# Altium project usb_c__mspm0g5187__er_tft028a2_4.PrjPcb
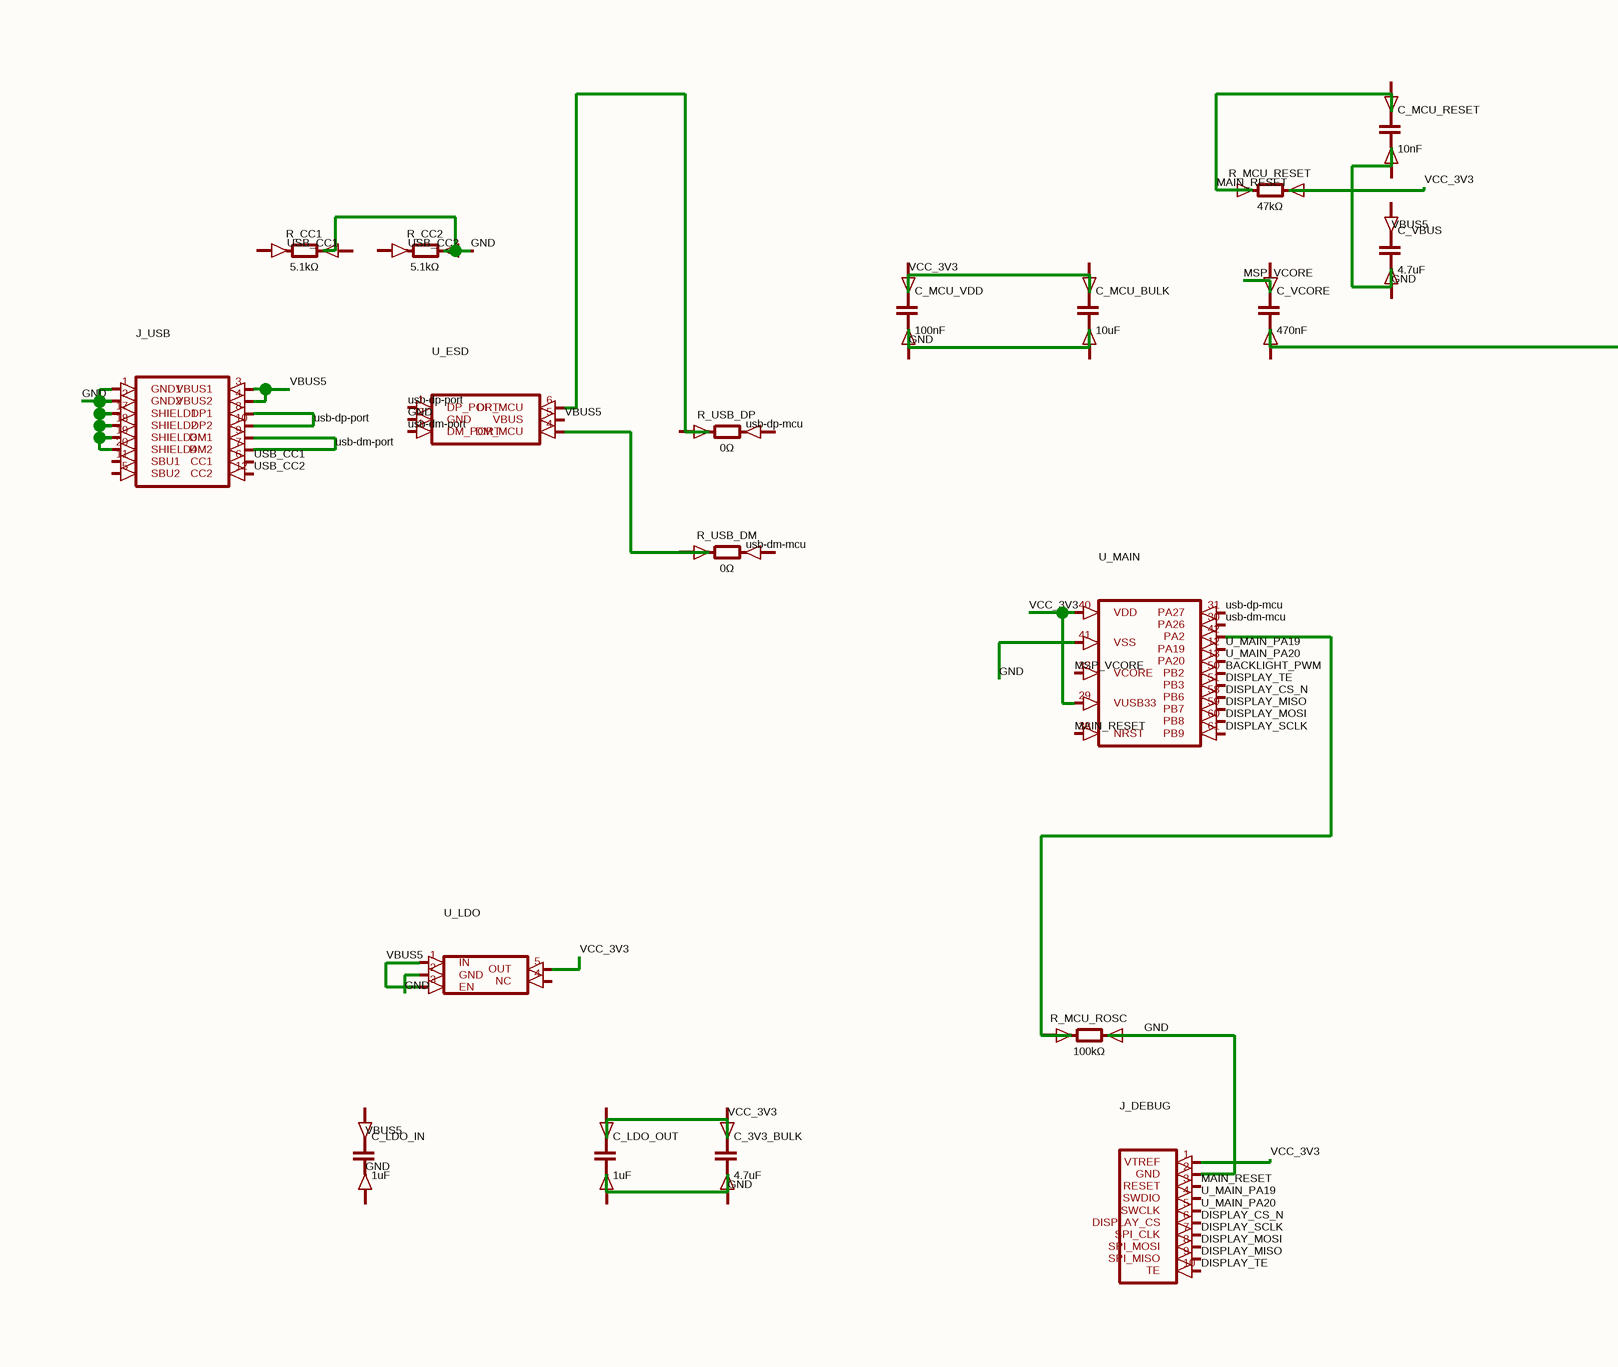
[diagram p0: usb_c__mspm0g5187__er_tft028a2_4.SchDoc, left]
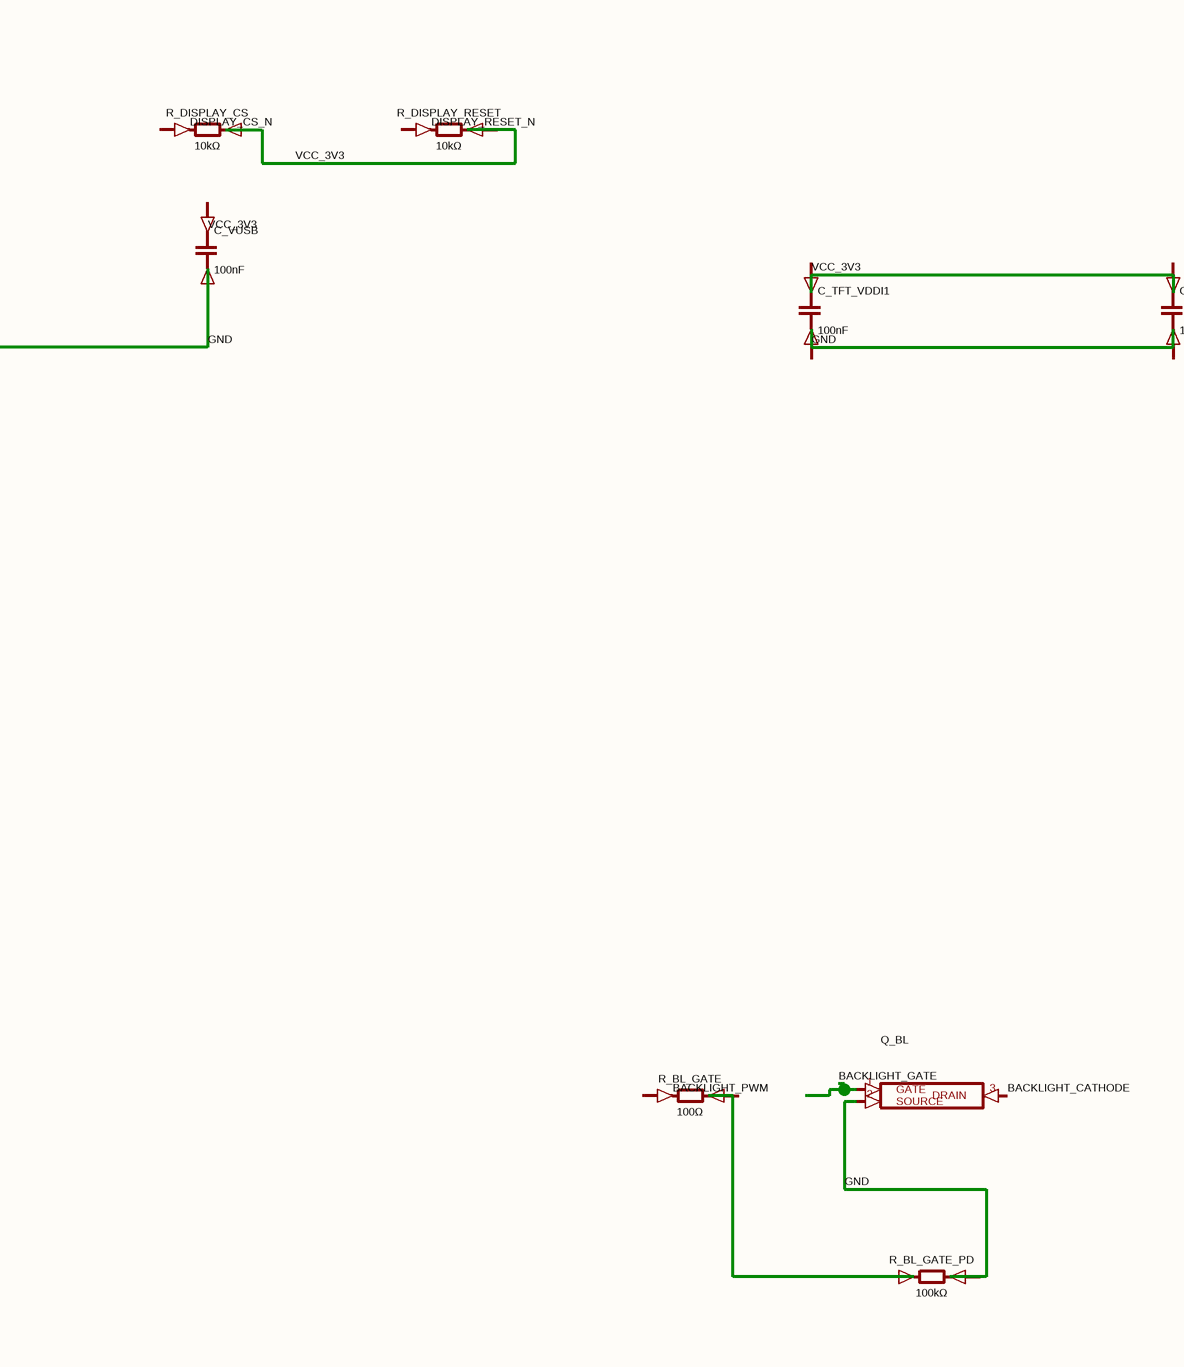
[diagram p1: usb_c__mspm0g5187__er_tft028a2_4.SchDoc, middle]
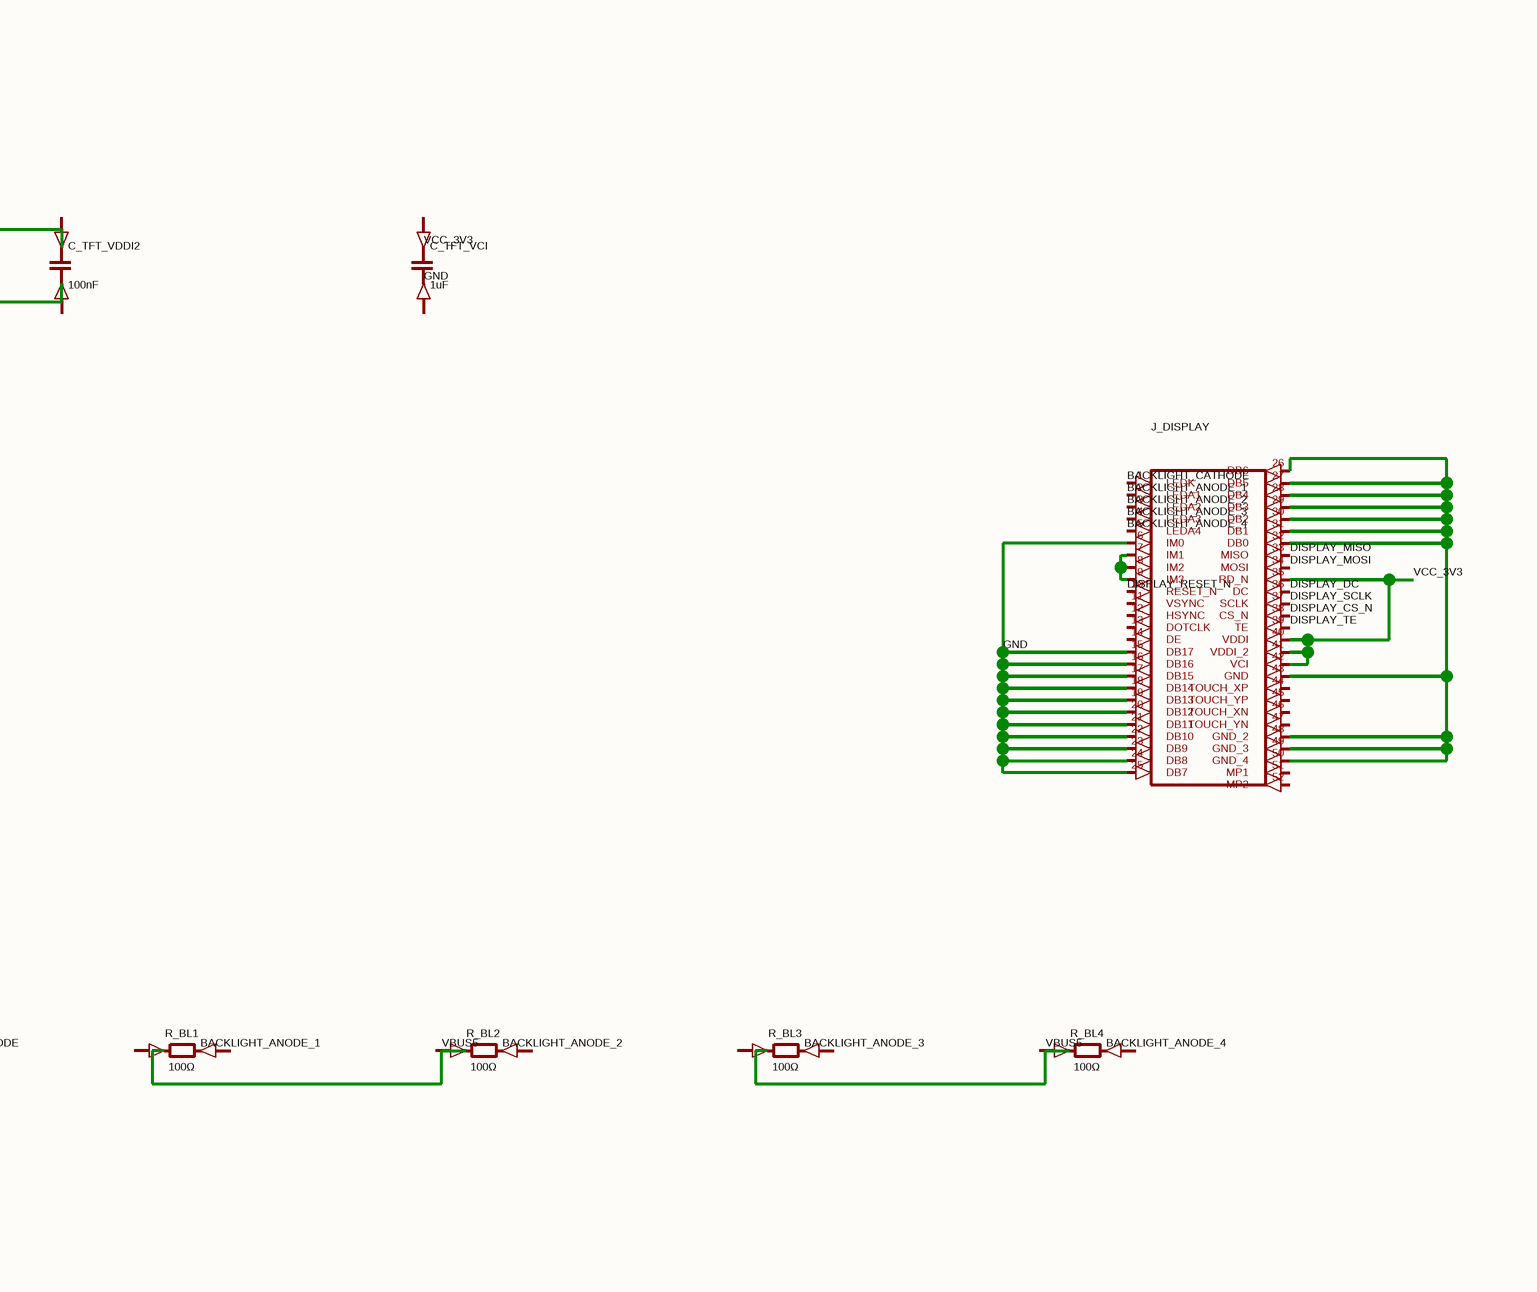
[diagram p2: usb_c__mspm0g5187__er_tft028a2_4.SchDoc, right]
1 sheet, 33 parts. Net scope: global (net labels, ports and power ports of the same name join across sheets).
Board file: usb_c__mspm0g5187__er_tft028a2_4.PcbDoc

## Sheet usb_c__mspm0g5187__er_tft028a2_4.SchDoc
size 389 x 150 mm

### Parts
C_3V3_BULK  4.7uF
C_LDO_IN  1uF
C_LDO_OUT  1uF
C_MCU_BULK  10uF
C_MCU_RESET  10nF
C_MCU_VDD  100nF
C_TFT_VCI  1uF
C_TFT_VDDI1  100nF
C_TFT_VDDI2  100nF
C_VBUS  4.7uF
C_VCORE  470nF
C_VUSB  100nF
J_DEBUG  (no value)
J_DISPLAY  (no value)
J_USB  (no value)
Q_BL  (no value)
R_BL1  100Ω
R_BL2  100Ω
R_BL3  100Ω
R_BL4  100Ω
R_BL_GATE  100Ω
R_BL_GATE_PD  100kΩ
R_CC1  5.1kΩ
R_CC2  5.1kΩ
R_DISPLAY_CS  10kΩ
R_DISPLAY_RESET  10kΩ
R_MCU_RESET  47kΩ
R_MCU_ROSC  100kΩ
R_USB_DM  0Ω
R_USB_DP  0Ω
U_ESD  (no value)
U_LDO  (no value)
U_MAIN  (no value)

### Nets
BACKLIGHT_ANODE_1: J_DISPLAY.2(LEDA1)
BACKLIGHT_ANODE_2: J_DISPLAY.3(LEDA2)
BACKLIGHT_ANODE_3: J_DISPLAY.4(LEDA3)
BACKLIGHT_ANODE_4: J_DISPLAY.5(LEDA4)
BACKLIGHT_CATHODE: J_DISPLAY.1(LEDK) Q_BL.3(DRAIN)
BACKLIGHT_GATE: Q_BL.1(GATE)
BACKLIGHT_PWM: U_MAIN.50(PB2)
DISPLAY_CS_N: J_DEBUG.6(DISPLAY_CS) J_DISPLAY.38(CS_N) U_MAIN.58(PB6)
DISPLAY_DC: J_DISPLAY.36(DC)
DISPLAY_MISO: J_DEBUG.9(SPI_MISO) J_DISPLAY.33(MISO) U_MAIN.59(PB7)
DISPLAY_MOSI: J_DEBUG.8(SPI_MOSI) J_DISPLAY.34(MOSI) U_MAIN.60(PB8)
DISPLAY_RESET_N: J_DISPLAY.10(RESET_N)
DISPLAY_SCLK: J_DEBUG.7(SPI_CLK) J_DISPLAY.37(SCLK) U_MAIN.61(PB9)
DISPLAY_TE: J_DEBUG.10(TE) J_DISPLAY.39(TE) U_MAIN.51(PB3)
GND: C_VUSB.2(cathode) J_DEBUG.1(VTREF) J_DEBUG.2(GND) J_DISPLAY.6(IM0) J_DISPLAY.15(DB17) J_DISPLAY.16(DB16) J_DISPLAY.17(DB15) J_DISPLAY.18(DB14) J_DISPLAY.19(DB13) J_DISPLAY.20(DB12) J_DISPLAY.21(DB11) J_DISPLAY.22(DB10) J_DISPLAY.23(DB9) J_DISPLAY.24(DB8) J_DISPLAY.25(DB7) J_DISPLAY.35(RD_N) J_DISPLAY.40(VDDI) J_DISPLAY.41(VDDI_2) J_DISPLAY.42(VCI) J_USB.1(GND1) J_USB.2(GND2) J_USB.3(VBUS1) J_USB.4(VBUS2) J_USB.17(SHIELD1) J_USB.18(SHIELD2) J_USB.19(SHIELD3) J_USB.20(SHIELD4) Q_BL.2(SOURCE) R_BL_GATE_PD.2(cathode) R_DISPLAY_CS.2(cathode) R_DISPLAY_RESET.2(cathode) R_MCU_RESET.2(cathode) R_MCU_ROSC.2(cathode) U_ESD.2(GND) U_ESD.5(VBUS) U_LDO.1(IN) U_LDO.2(GND) U_LDO.3(EN) U_LDO.5(OUT) U_MAIN.29(VUSB33) U_MAIN.40(VDD) U_MAIN.41(VSS)  [also labelled VBUS5, VCC_3V3]
MAIN_RESET: J_DEBUG.3(RESET) R_MCU_RESET.1(anode) U_MAIN.38(NRST)
MSP_VCORE: U_MAIN.32(VCORE)
U_MAIN_PA19: J_DEBUG.4(SWDIO) U_MAIN.12(PA19)
U_MAIN_PA20: J_DEBUG.5(SWCLK) U_MAIN.13(PA20)
usb-dm-mcu: U_MAIN.30(PA26)
usb-dm-port: J_USB.7(DM2) J_USB.9(DM1) U_ESD.3(DM_PORT)
usb-dp-mcu: U_MAIN.31(PA27)
usb-dp-port: J_USB.8(DP1) J_USB.10(DP2) U_ESD.1(DP_PORT)
USB_CC1: J_USB.6(CC1)
USB_CC2: J_USB.12(CC2)
NetJ_DISPLAY_7: J_DISPLAY.7(IM1) J_DISPLAY.8(IM2) J_DISPLAY.9(IM3)
NetJ_DISPLAY_26: J_DISPLAY.26(DB6) J_DISPLAY.27(DB5) J_DISPLAY.28(DB4) J_DISPLAY.29(DB3) J_DISPLAY.30(DB2) J_DISPLAY.31(DB1) J_DISPLAY.32(DB0) J_DISPLAY.43(GND) J_DISPLAY.48(GND_2) J_DISPLAY.49(GND_3) J_DISPLAY.50(GND_4)
NetR_MCU_ROSC_1: R_MCU_ROSC.1(anode) U_MAIN.42(PA2)
NetR_USB_DM_1: R_USB_DM.1(anode) U_ESD.4(DM_MCU)

Not connected (* = marked no-connect by the designer): C_3V3_BULK 1(anode) 2(cathode); C_LDO_IN 1(anode) 2(cathode); C_LDO_OUT 1(anode) 2(cathode); C_MCU_BULK 1(anode) 2(cathode); C_MCU_RESET 1(anode) 2(cathode); C_MCU_VDD 1(anode) 2(cathode); C_TFT_VCI 1(anode) 2(cathode); C_TFT_VDDI1 1(anode) 2(cathode); C_TFT_VDDI2 1(anode) 2(cathode); C_VBUS 1(anode) 2(cathode); C_VCORE 1(anode) 2(cathode); C_VUSB 1(anode); J_DISPLAY 11(VSYNC) 12(HSYNC) 13(DOTCLK) 14(DE) 44(TOUCH_XP) 45(TOUCH_YP) 46(TOUCH_XN) 47(TOUCH_YN) 51(MP1) 52(MP2); J_USB 5(SBU2) 11(SBU1); R_BL1 1(anode) 2(cathode); R_BL2 1(anode) 2(cathode); R_BL3 1(anode) 2(cathode); R_BL4 1(anode) 2(cathode); R_BL_GATE 1(anode) 2(cathode); R_BL_GATE_PD 1(anode); R_CC1 1(anode) 2(cathode); R_CC2 1(anode) 2(cathode); R_DISPLAY_CS 1(anode); R_DISPLAY_RESET 1(anode); R_USB_DM 2(cathode); R_USB_DP 1(anode) 2(cathode); U_ESD 6(DP_MCU); U_LDO 4(NC)

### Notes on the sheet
- Labels drawn without touching a wire or pin: BACKLIGHT_ANODE_1, BACKLIGHT_ANODE_2, BACKLIGHT_ANODE_3, BACKLIGHT_ANODE_4, BACKLIGHT_PWM, DISPLAY_CS_N, DISPLAY_RESET_N, GND, usb-dm-mcu, usb-dp-mcu, USB_CC1, USB_CC2, VBUS5, VCC_3V3

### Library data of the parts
C_3V3_BULK C_LDO_IN C_LDO_OUT C_MCU_BULK C_MCU_RESET C_MCU_VDD C_TFT_VCI C_TFT_VDDI1 C_TFT_VDDI2 C_VBUS C_VCORE C_VUSB = capacitor_down
J_DEBUG = J_DEBUG
J_DISPLAY = J_DISPLAY
J_USB = J_USB
Q_BL = Q_BL
R_BL1-R_BL4 R_BL_GATE R_BL_GATE_PD R_CC1 R_CC2 R_DISPLAY_CS R_DISPLAY_RESET R_MCU_RESET R_MCU_ROSC R_USB_DM R_USB_DP = boxresistor_right
U_ESD = U_ESD
U_LDO = U_LDO
U_MAIN = U_MAIN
